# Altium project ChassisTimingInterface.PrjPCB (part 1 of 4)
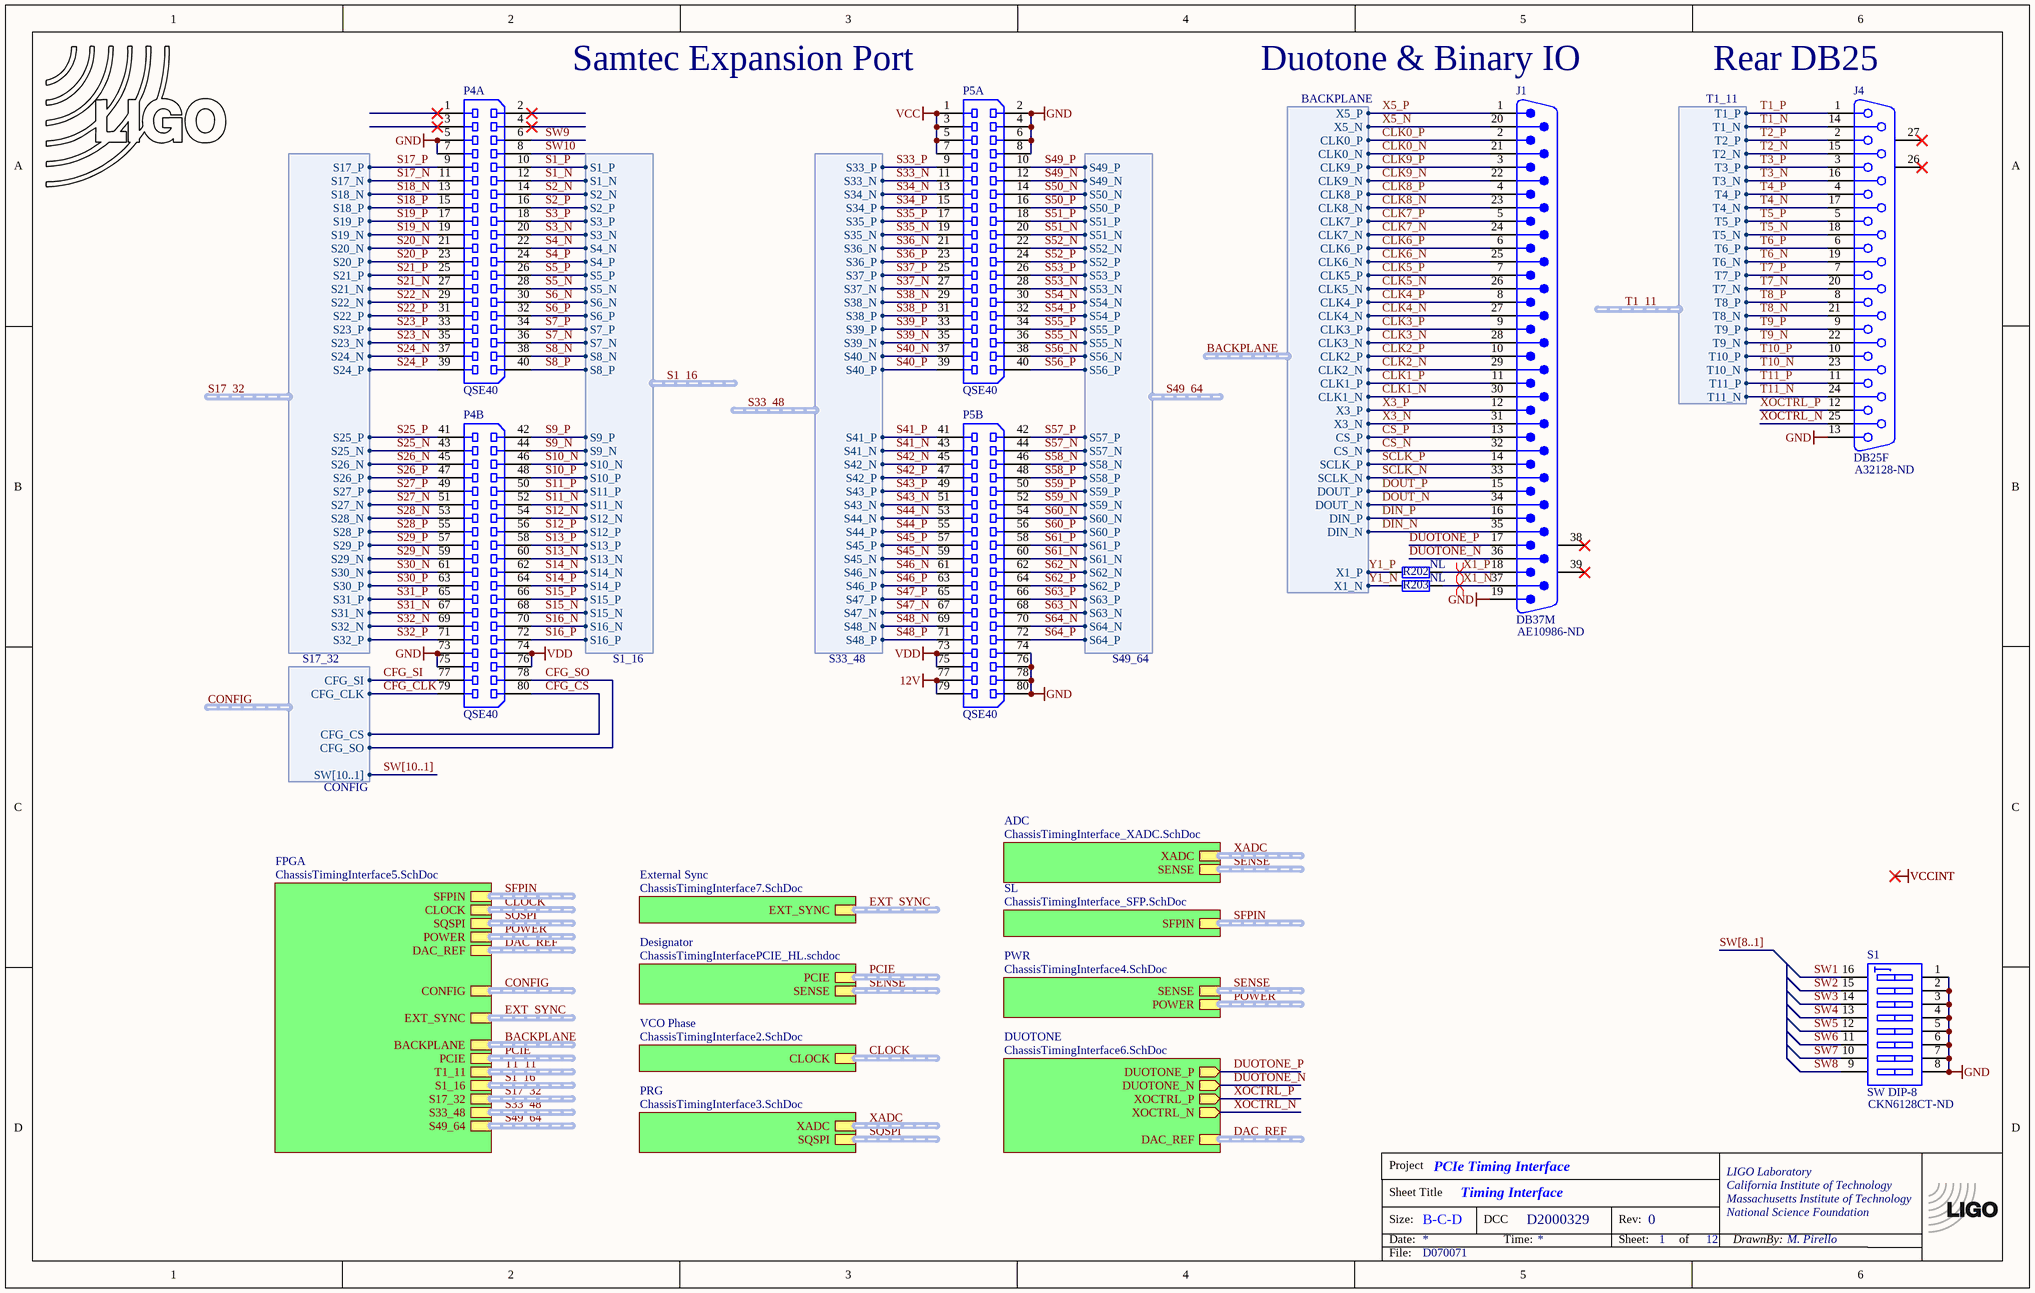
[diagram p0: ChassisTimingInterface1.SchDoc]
DCC: D2000329; Eng: M. Pirello; PROJECT: PCIe Timing Interface; REV: 0; SHEETSIZE: B-C-D
12 sheets, 566 parts. Net scope: hierarchical (ports join the sheet entries above them; power ports are global).
Board file: ChassisTimingInterface.PCBDOC
Sheets:
  ChassisTimingInterface1.SchDoc
    VCO Phase = ChassisTimingInterface2.SchDoc
    PWR = ChassisTimingInterface4.SchDoc
    PRG = ChassisTimingInterface3.SchDoc
    FPGA = ChassisTimingInterface5.SchDoc
      FPGA = FPGA_ARTIX7.SchDoc
    Designator = ChassisTimingInterfacePCIE_HL.SchDoc
      ChassisTimingInterfacePCIE = ChassisTimingInterfacePCIE.SchDoc
    DUOTONE = ChassisTimingInterface6.SchDoc
    SL = ChassisTimingInterface_SFP.SchDoc
    External Sync = ChassisTimingInterface7.SchDoc
    ADC = ChassisTimingInterface_XADC.SchDoc

## Sheet ChassisTimingInterface1.SchDoc: Timing Interface
size B; Engineer: Daniel Sigg; DocumentNumber: 1; Revision: C; SheetNumber: 1; SheetTotal: 12; PageSetup: Record=PageOptions¦CenterHorizontal=True¦CenterVertical=True¦PrintScale=0.72¦XCorrection=1.00¦YCorrection=1.00¦PrintKind=0¦BorderSize=5000000¦LeftOffset=0¦BottomOffset=0¦Orientation=2¦PaperLength=1000¦PaperWidth=1000¦Scale=100¦PaperSource=7¦PrintQuality=-4¦MediaType=1¦DitherType=10¦PaperKind=Tabloid¦PrintScaleMode=1

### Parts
(Parts that share a designator on the sheet are numbered #1, #2 ... from top to bottom, then left to right.)
*#1  TitleBlock  (value not drawn)  (graphical)
J1  DB37M  Supplier Part Number 1: AE10986-ND  [DB37M-RA]
J4  DB25F  Supplier Part Number 1: A32128-ND  [DB25F-RA]
LOGO1  LIGO logo  [LIGO-LOGO-SM]  (value not drawn)  (no BOM)
P4  QSE40  [QSE040]  (parts A,B of 2)
P5  QSE40  [QSE040]  (parts A,B of 2)
R202  NL  [CR1005-0402]
R203  NL  [CR1005-0402]
S1  SW DIP-8  Supplier Part Number 1: CKN6128CT-ND  [DIP_SW_8WAY_SMD_SIDE]

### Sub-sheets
ADC = ChassisTimingInterface_XADC.SchDoc: XADC (harness XADC), SENSE (harness SENSE)
Designator = ChassisTimingInterfacePCIE_HL.schdoc: PCIE (harness PCIE), SENSE (harness SENSE)
DUOTONE = ChassisTimingInterface6.SchDoc: DUOTONE_N (out), DUOTONE_P (out), XOCTRL_P (out), XOCTRL_N (out), DAC_REF (harness DAC_REF)
External Sync = ChassisTimingInterface7.SchDoc: EXT_SYNC (harness EXT_SYNC)
FPGA = ChassisTimingInterface5.SchDoc: S1_16 (harness S1_16), S17_32 (harness S17_32), S33_48 (harness S33_48), S49_64 (harness S49_64), T1_11 (harness T1_11), CLOCK (harness CLOCK), PCIE (harness PCIE), POWER (harness POWER), SQSPI (harness SQSPI), DAC_REF (harness DAC_REF), CONFIG (harness CONFIG), BACKPLANE (harness BACKPLANE), SFPIN (harness SFPIN), EXT_SYNC (harness EXT_SYNC)
PRG = ChassisTimingInterface3.SchDoc: SQSPI (harness SQSPI), XADC (harness XADC)
PWR = ChassisTimingInterface4.SchDoc: POWER (harness POWER), SENSE (harness SENSE)
SL = ChassisTimingInterface_SFP.SchDoc: SFPIN (harness SFPIN)
VCO Phase = ChassisTimingInterface2.SchDoc: CLOCK (harness CLOCK)

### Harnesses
S1_16: S1_N, S1_P, S2_N, S2_P, S3_N, S3_P, S4_N, S4_P, S5_N, S5_P, S6_N, S6_P, S7_N, S7_P, S8_N, S8_P, S9_N, S9_P, S10_N, S10_P, S11_N, S11_P, S12_N, S12_P, S13_N, S13_P, S14_N, S14_P, S15_N, S15_P, S16_N, S16_P
S17_32: S17_N, S17_P, S18_N, S18_P, S19_N, S19_P, S20_N, S20_P, S21_N, S21_P, S22_N, S22_P, S23_N, S23_P, S24_N, S24_P, S25_N, S25_P, S26_N, S26_P, S27_N, S27_P, S28_N, S28_P, S29_N, S29_P, S30_N, S30_P, S31_N, S31_P, S32_N, S32_P
S33_48: S33_P, S33_N, S34_P, S34_N, S35_P, S35_N, S36_N, S36_P, S37_P, S37_N, S38_N, S38_P, S39_P, S39_N, S40_N, S40_P, S41_P, S41_N, S42_N, S42_P, S43_P, S43_N, S44_N, S44_P, S45_P, S45_N, S46_N, S46_P, S47_P, S47_N, S48_N, S48_P
S49_64: S49_P, S49_N, S50_N, S50_P, S51_P, S51_N, S52_N, S52_P, S53_P, S53_N, S54_N, S54_P, S55_P, S55_N, S56_N, S56_P, S57_P, S57_N, S58_N, S58_P, S59_P, S59_N, S60_N, S60_P, S61_P, S61_N, S62_N, S62_P, S63_P, S63_N, S64_N, S64_P
T1_11: T1_P, T1_N, T2_P, T2_N, T3_P, T3_N, T4_P, T4_N, T5_P, T5_N, T6_P, T6_N, T7_P, T7_N, T8_P, T8_N, T9_P, T9_N, T10_P, T10_N, T11_P, T11_N
CONFIG: CFG_CLK, CFG_CS, CFG_SI, CFG_SO, SW[10..1]
BACKPLANE: DIN_N, DIN_P, DOUT_N, DOUT_P, SCLK_N, SCLK_P, CS_N, CS_P, X3_N, X3_P, CLK1_N, CLK1_P, CLK2_N, CLK2_P, CLK3_N, CLK3_P, CLK4_N, CLK4_P, CLK5_N, CLK5_P, CLK6_N, CLK6_P, CLK7_N, CLK7_P, CLK8_N, CLK8_P, CLK9_N, CLK9_P, CLK0_N, CLK0_P, X5_N, X5_P, X1_P, X1_N

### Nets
12V: P5.77 P5.79
GND: J1.19 J4.13 P4.5 P4.7 P4.73 P4.75 P4.81 P4.82 P4.83 P4.84 P4.85 P4.86 P4.87 P4.88 P5.2 P5.4 P5.6 P5.8 P5.74 P5.76 P5.78 P5.80 P5.81 P5.82 P5.83 P5.84 P5.85 P5.86 P5.87 P5.88 S1.1(A1) S1.2(A2) S1.3(A3) S1.4(A4) S1.5(A5) S1.6(A6) S1.7(A7) S1.8(A8)
VCC: P5.1 P5.3 P5.5 P5.7
VDD: P4.74 P4.76 P5.73 P5.75
CFG_CLK: P4.79 ; sheet FPGA/CONFIG.CFG_CLK
CFG_CS: P4.80 ; sheet FPGA/CONFIG.CFG_CS
CFG_SI: P4.77 ; sheet FPGA/CONFIG.CFG_SI
CFG_SO: P4.78 ; sheet FPGA/CONFIG.CFG_SO
CLK0_N: J1.21 ; sheet FPGA/BACKPLANE.CLK0_N  [project net BACKPLANE.CLK0_N]
CLK0_P: J1.2 ; sheet FPGA/BACKPLANE.CLK0_P  [project net BACKPLANE.CLK0_P]
CLK1_N: J1.30 ; sheet FPGA/BACKPLANE.CLK1_N  [project net BACKPLANE.CLK1_N]
CLK1_P: J1.11 ; sheet FPGA/BACKPLANE.CLK1_P  [project net BACKPLANE.CLK1_P]
CLK2_N: J1.29 ; sheet FPGA/BACKPLANE.CLK2_N  [project net BACKPLANE.CLK2_N]
CLK2_P: J1.10 ; sheet FPGA/BACKPLANE.CLK2_P  [project net BACKPLANE.CLK2_P]
CLK3_N: J1.28 ; sheet FPGA/BACKPLANE.CLK3_N  [project net BACKPLANE.CLK3_N]
CLK3_P: J1.9 ; sheet FPGA/BACKPLANE.CLK3_P  [project net BACKPLANE.CLK3_P]
CLK4_N: J1.27 ; sheet FPGA/BACKPLANE.CLK4_N  [project net BACKPLANE.CLK4_N]
CLK4_P: J1.8 ; sheet FPGA/BACKPLANE.CLK4_P  [project net BACKPLANE.CLK4_P]
CLK5_N: J1.26 ; sheet FPGA/BACKPLANE.CLK5_N  [project net BACKPLANE.CLK5_N]
CLK5_P: J1.7 ; sheet FPGA/BACKPLANE.CLK5_P  [project net BACKPLANE.CLK5_P]
CLK6_N: J1.25 ; sheet FPGA/BACKPLANE.CLK6_N  [project net BACKPLANE.CLK6_N]
CLK6_P: J1.6 ; sheet FPGA/BACKPLANE.CLK6_P  [project net BACKPLANE.CLK6_P]
CLK7_N: J1.24 ; sheet FPGA/BACKPLANE.CLK7_N  [project net BACKPLANE.CLK7_N]
CLK7_P: J1.5 ; sheet FPGA/BACKPLANE.CLK7_P  [project net BACKPLANE.CLK7_P]
CLK8_N: J1.23 ; sheet FPGA/BACKPLANE.CLK8_N  [project net BACKPLANE.CLK8_N]
CLK8_P: J1.4 ; sheet FPGA/BACKPLANE.CLK8_P  [project net BACKPLANE.CLK8_P]
CLK9_N: J1.22 ; sheet FPGA/BACKPLANE.CLK9_N  [project net BACKPLANE.CLK9_N]
CLK9_P: J1.3 ; sheet FPGA/BACKPLANE.CLK9_P  [project net BACKPLANE.CLK9_P]
CS_N: J1.32 ; sheet FPGA/BACKPLANE.CS_N  [project net BACKPLANE.CS_N]
CS_P: J1.13 ; sheet FPGA/BACKPLANE.CS_P  [project net BACKPLANE.CS_P]
DIN_N: J1.35 ; sheet FPGA/BACKPLANE.DIN_N  [project net BACKPLANE.DIN_N]
DIN_P: J1.16 ; sheet FPGA/BACKPLANE.DIN_P  [project net BACKPLANE.DIN_P]
DOUT_N: J1.34 ; sheet FPGA/BACKPLANE.DOUT_N  [project net BACKPLANE.DOUT_N]
DOUT_P: J1.15 ; sheet FPGA/BACKPLANE.DOUT_P  [project net BACKPLANE.DOUT_P]
DUOTONE_N: J1.36 ; sheet DUOTONE/DUOTONE_N
DUOTONE_P: J1.17 ; sheet DUOTONE/DUOTONE_P
S1_N: P4.12 ; sheet FPGA/S1_16.S1_N  [project net S1_16.S1_N]
S1_P: P4.10 ; sheet FPGA/S1_16.S1_P  [project net S1_16.S1_P]
S2_N: P4.14 ; sheet FPGA/S1_16.S2_N  [project net S1_16.S2_N]
S2_P: P4.16 ; sheet FPGA/S1_16.S2_P  [project net S1_16.S2_P]
S3_N: P4.20 ; sheet FPGA/S1_16.S3_N  [project net S1_16.S3_N]
S3_P: P4.18 ; sheet FPGA/S1_16.S3_P  [project net S1_16.S3_P]
S4_N: P4.22 ; sheet FPGA/S1_16.S4_N  [project net S1_16.S4_N]
S4_P: P4.24 ; sheet FPGA/S1_16.S4_P  [project net S1_16.S4_P]
S5_N: P4.28 ; sheet FPGA/S1_16.S5_N  [project net S1_16.S5_N]
S5_P: P4.26 ; sheet FPGA/S1_16.S5_P  [project net S1_16.S5_P]
S6_N: P4.30 ; sheet FPGA/S1_16.S6_N  [project net S1_16.S6_N]
S6_P: P4.32 ; sheet FPGA/S1_16.S6_P  [project net S1_16.S6_P]
S7_N: P4.36 ; sheet FPGA/S1_16.S7_N  [project net S1_16.S7_N]
S7_P: P4.34 ; sheet FPGA/S1_16.S7_P  [project net S1_16.S7_P]
S8_N: P4.38 ; sheet FPGA/S1_16.S8_N  [project net S1_16.S8_N]
S8_P: P4.40 ; sheet FPGA/S1_16.S8_P  [project net S1_16.S8_P]
S9_N: P4.44 ; sheet FPGA/S1_16.S9_N  [project net S1_16.S9_N]
S9_P: P4.42 ; sheet FPGA/S1_16.S9_P  [project net S1_16.S9_P]
S10_N: P4.46 ; sheet FPGA/S1_16.S10_N
S10_P: P4.48 ; sheet FPGA/S1_16.S10_P
S11_N: P4.52 ; sheet FPGA/S1_16.S11_N
S11_P: P4.50 ; sheet FPGA/S1_16.S11_P
S12_N: P4.54 ; sheet FPGA/S1_16.S12_N
S12_P: P4.56 ; sheet FPGA/S1_16.S12_P
S13_N: P4.60 ; sheet FPGA/S1_16.S13_N
S13_P: P4.58 ; sheet FPGA/S1_16.S13_P
S14_N: P4.62 ; sheet FPGA/S1_16.S14_N
S14_P: P4.64 ; sheet FPGA/S1_16.S14_P
S15_N: P4.68 ; sheet FPGA/S1_16.S15_N
S15_P: P4.66 ; sheet FPGA/S1_16.S15_P
S16_N: P4.70 ; sheet FPGA/S1_16.S16_N
S16_P: P4.72 ; sheet FPGA/S1_16.S16_P
S17_N: P4.11 ; sheet FPGA/S17_32.S17_N  [project net S17_32.S17_N]
S17_P: P4.9 ; sheet FPGA/S17_32.S17_P  [project net S17_32.S17_P]
S18_N: P4.13 ; sheet FPGA/S17_32.S18_N  [project net S17_32.S18_N]
S18_P: P4.15 ; sheet FPGA/S17_32.S18_P  [project net S17_32.S18_P]
S19_N: P4.19 ; sheet FPGA/S17_32.S19_N  [project net S17_32.S19_N]
S19_P: P4.17 ; sheet FPGA/S17_32.S19_P  [project net S17_32.S19_P]
S20_N: P4.21 ; sheet FPGA/S17_32.S20_N  [project net S17_32.S20_N]
S20_P: P4.23 ; sheet FPGA/S17_32.S20_P  [project net S17_32.S20_P]
S21_N: P4.27 ; sheet FPGA/S17_32.S21_N  [project net S17_32.S21_N]
S21_P: P4.25 ; sheet FPGA/S17_32.S21_P  [project net S17_32.S21_P]
S22_N: P4.29 ; sheet FPGA/S17_32.S22_N  [project net S17_32.S22_N]
S22_P: P4.31 ; sheet FPGA/S17_32.S22_P  [project net S17_32.S22_P]
S23_N: P4.35 ; sheet FPGA/S17_32.S23_N  [project net S17_32.S23_N]
S23_P: P4.33 ; sheet FPGA/S17_32.S23_P  [project net S17_32.S23_P]
S24_N: P4.37 ; sheet FPGA/S17_32.S24_N  [project net S17_32.S24_N]
S24_P: P4.39 ; sheet FPGA/S17_32.S24_P  [project net S17_32.S24_P]
S25_N: P4.43 ; sheet FPGA/S17_32.S25_N  [project net S17_32.S25_N]
S25_P: P4.41 ; sheet FPGA/S17_32.S25_P  [project net S17_32.S25_P]
S26_N: P4.45 ; sheet FPGA/S17_32.S26_N  [project net S17_32.S26_N]
S26_P: P4.47 ; sheet FPGA/S17_32.S26_P  [project net S17_32.S26_P]
S27_N: P4.51 ; sheet FPGA/S17_32.S27_N  [project net S17_32.S27_N]
S27_P: P4.49 ; sheet FPGA/S17_32.S27_P  [project net S17_32.S27_P]
S28_N: P4.53 ; sheet FPGA/S17_32.S28_N  [project net S17_32.S28_N]
S28_P: P4.55 ; sheet FPGA/S17_32.S28_P  [project net S17_32.S28_P]
S29_N: P4.59 ; sheet FPGA/S17_32.S29_N  [project net S17_32.S29_N]
S29_P: P4.57 ; sheet FPGA/S17_32.S29_P  [project net S17_32.S29_P]
S30_N: P4.61 ; sheet FPGA/S17_32.S30_N  [project net S17_32.S30_N]
S30_P: P4.63 ; sheet FPGA/S17_32.S30_P  [project net S17_32.S30_P]
S31_N: P4.67 ; sheet FPGA/S17_32.S31_N  [project net S17_32.S31_N]
S31_P: P4.65 ; sheet FPGA/S17_32.S31_P  [project net S17_32.S31_P]
S32_N: P4.69 ; sheet FPGA/S17_32.S32_N  [project net S17_32.S32_N]
S32_P: P4.71 ; sheet FPGA/S17_32.S32_P  [project net S17_32.S32_P]
S33_N: P5.11 ; sheet FPGA/S33_48.S33_N  [project net S33_48.S33_N]
S33_P: P5.9 ; sheet FPGA/S33_48.S33_P  [project net S33_48.S33_P]
S34_N: P5.13 ; sheet FPGA/S33_48.S34_N  [project net S33_48.S34_N]
S34_P: P5.15 ; sheet FPGA/S33_48.S34_P  [project net S33_48.S34_P]
S35_N: P5.19 ; sheet FPGA/S33_48.S35_N  [project net S33_48.S35_N]
S35_P: P5.17 ; sheet FPGA/S33_48.S35_P  [project net S33_48.S35_P]
S36_N: P5.21 ; sheet FPGA/S33_48.S36_N  [project net S33_48.S36_N]
S36_P: P5.23 ; sheet FPGA/S33_48.S36_P  [project net S33_48.S36_P]
S37_N: P5.27 ; sheet FPGA/S33_48.S37_N  [project net S33_48.S37_N]
S37_P: P5.25 ; sheet FPGA/S33_48.S37_P  [project net S33_48.S37_P]
S38_N: P5.29 ; sheet FPGA/S33_48.S38_N  [project net S33_48.S38_N]
S38_P: P5.31 ; sheet FPGA/S33_48.S38_P  [project net S33_48.S38_P]
S39_N: P5.35 ; sheet FPGA/S33_48.S39_N  [project net S33_48.S39_N]
S39_P: P5.33 ; sheet FPGA/S33_48.S39_P  [project net S33_48.S39_P]
S40_N: P5.37 ; sheet FPGA/S33_48.S40_N  [project net S33_48.S40_N]
S40_P: P5.39 ; sheet FPGA/S33_48.S40_P  [project net S33_48.S40_P]
S41_N: P5.43 ; sheet FPGA/S33_48.S41_N  [project net S33_48.S41_N]
S41_P: P5.41 ; sheet FPGA/S33_48.S41_P  [project net S33_48.S41_P]
S42_N: P5.45 ; sheet FPGA/S33_48.S42_N  [project net S33_48.S42_N]
S42_P: P5.47 ; sheet FPGA/S33_48.S42_P  [project net S33_48.S42_P]
S43_N: P5.51 ; sheet FPGA/S33_48.S43_N  [project net S33_48.S43_N]
S43_P: P5.49 ; sheet FPGA/S33_48.S43_P  [project net S33_48.S43_P]
S44_N: P5.53 ; sheet FPGA/S33_48.S44_N  [project net S33_48.S44_N]
S44_P: P5.55 ; sheet FPGA/S33_48.S44_P  [project net S33_48.S44_P]
S45_N: P5.59 ; sheet FPGA/S33_48.S45_N  [project net S33_48.S45_N]
S45_P: P5.57 ; sheet FPGA/S33_48.S45_P  [project net S33_48.S45_P]
S46_N: P5.61 ; sheet FPGA/S33_48.S46_N  [project net S33_48.S46_N]
S46_P: P5.63 ; sheet FPGA/S33_48.S46_P  [project net S33_48.S46_P]
S47_N: P5.67 ; sheet FPGA/S33_48.S47_N  [project net S33_48.S47_N]
S47_P: P5.65 ; sheet FPGA/S33_48.S47_P  [project net S33_48.S47_P]
S48_N: P5.69 ; sheet FPGA/S33_48.S48_N  [project net S33_48.S48_N]
S48_P: P5.71 ; sheet FPGA/S33_48.S48_P  [project net S33_48.S48_P]
S49_N: P5.12 ; sheet FPGA/S49_64.S49_N  [project net S49_64.S49_N]
S49_P: P5.10 ; sheet FPGA/S49_64.S49_P  [project net S49_64.S49_P]
S50_N: P5.14 ; sheet FPGA/S49_64.S50_N  [project net S49_64.S50_N]
S50_P: P5.16 ; sheet FPGA/S49_64.S50_P  [project net S49_64.S50_P]
S51_N: P5.20 ; sheet FPGA/S49_64.S51_N  [project net S49_64.S51_N]
S51_P: P5.18 ; sheet FPGA/S49_64.S51_P  [project net S49_64.S51_P]
S52_N: P5.22 ; sheet FPGA/S49_64.S52_N  [project net S49_64.S52_N]
S52_P: P5.24 ; sheet FPGA/S49_64.S52_P  [project net S49_64.S52_P]
S53_N: P5.28 ; sheet FPGA/S49_64.S53_N  [project net S49_64.S53_N]
S53_P: P5.26 ; sheet FPGA/S49_64.S53_P  [project net S49_64.S53_P]
S54_N: P5.30 ; sheet FPGA/S49_64.S54_N  [project net S49_64.S54_N]
S54_P: P5.32 ; sheet FPGA/S49_64.S54_P  [project net S49_64.S54_P]
S55_N: P5.36 ; sheet FPGA/S49_64.S55_N  [project net S49_64.S55_N]
S55_P: P5.34 ; sheet FPGA/S49_64.S55_P  [project net S49_64.S55_P]
S56_N: P5.38 ; sheet FPGA/S49_64.S56_N  [project net S49_64.S56_N]
S56_P: P5.40 ; sheet FPGA/S49_64.S56_P  [project net S49_64.S56_P]
S57_N: P5.44 ; sheet FPGA/S49_64.S57_N  [project net S49_64.S57_N]
S57_P: P5.42 ; sheet FPGA/S49_64.S57_P  [project net S49_64.S57_P]
S58_N: P5.46 ; sheet FPGA/S49_64.S58_N  [project net S49_64.S58_N]
S58_P: P5.48 ; sheet FPGA/S49_64.S58_P  [project net S49_64.S58_P]
S59_N: P5.52 ; sheet FPGA/S49_64.S59_N  [project net S49_64.S59_N]
S59_P: P5.50 ; sheet FPGA/S49_64.S59_P  [project net S49_64.S59_P]
S60_N: P5.54 ; sheet FPGA/S49_64.S60_N  [project net S49_64.S60_N]
S60_P: P5.56 ; sheet FPGA/S49_64.S60_P  [project net S49_64.S60_P]
S61_N: P5.60 ; sheet FPGA/S49_64.S61_N  [project net S49_64.S61_N]
S61_P: P5.58 ; sheet FPGA/S49_64.S61_P  [project net S49_64.S61_P]
S62_N: P5.62 ; sheet FPGA/S49_64.S62_N  [project net S49_64.S62_N]
S62_P: P5.64 ; sheet FPGA/S49_64.S62_P  [project net S49_64.S62_P]
S63_N: P5.68 ; sheet FPGA/S49_64.S63_N  [project net S49_64.S63_N]
S63_P: P5.66 ; sheet FPGA/S49_64.S63_P  [project net S49_64.S63_P]
S64_N: P5.70 ; sheet FPGA/S49_64.S64_N  [project net S49_64.S64_N]
S64_P: P5.72 ; sheet FPGA/S49_64.S64_P  [project net S49_64.S64_P]
SCLK_N: J1.33 ; sheet FPGA/BACKPLANE.SCLK_N  [project net BACKPLANE.SCLK_N]
SCLK_P: J1.14 ; sheet FPGA/BACKPLANE.SCLK_P  [project net BACKPLANE.SCLK_P]
SW1: S1.16(B1)
SW2: S1.15(B2)
SW3: S1.14(B3)
SW4: S1.13(B4)
SW5: S1.12(B5)
SW6: S1.11(B6)
SW7: S1.10(B7)
SW8: S1.9(B8)
SW9: P4.6
SW10: P4.8
T1_N: J4.14 ; sheet FPGA/T1_11.T1_N  [project net T1_11.T1_N]
T1_P: J4.1 ; sheet FPGA/T1_11.T1_P  [project net T1_11.T1_P]
T2_N: J4.15 ; sheet FPGA/T1_11.T2_N  [project net T1_11.T2_N]
T2_P: J4.2 ; sheet FPGA/T1_11.T2_P  [project net T1_11.T2_P]
T3_N: J4.16 ; sheet FPGA/T1_11.T3_N  [project net T1_11.T3_N]
T3_P: J4.3 ; sheet FPGA/T1_11.T3_P  [project net T1_11.T3_P]
T4_N: J4.17 ; sheet FPGA/T1_11.T4_N  [project net T1_11.T4_N]
T4_P: J4.4 ; sheet FPGA/T1_11.T4_P  [project net T1_11.T4_P]
T5_N: J4.18 ; sheet FPGA/T1_11.T5_N  [project net T1_11.T5_N]
T5_P: J4.5 ; sheet FPGA/T1_11.T5_P  [project net T1_11.T5_P]
T6_N: J4.19 ; sheet FPGA/T1_11.T6_N  [project net T1_11.T6_N]
T6_P: J4.6 ; sheet FPGA/T1_11.T6_P  [project net T1_11.T6_P]
T7_N: J4.20 ; sheet FPGA/T1_11.T7_N  [project net T1_11.T7_N]
T7_P: J4.7 ; sheet FPGA/T1_11.T7_P  [project net T1_11.T7_P]
T8_N: J4.21 ; sheet FPGA/T1_11.T8_N  [project net T1_11.T8_N]
T8_P: J4.8 ; sheet FPGA/T1_11.T8_P  [project net T1_11.T8_P]
T9_N: J4.22 ; sheet FPGA/T1_11.T9_N  [project net T1_11.T9_N]
T9_P: J4.9 ; sheet FPGA/T1_11.T9_P  [project net T1_11.T9_P]
T10_N: J4.23 ; sheet FPGA/T1_11.T10_N
T10_P: J4.10 ; sheet FPGA/T1_11.T10_P
T11_N: J4.24 ; sheet FPGA/T1_11.T11_N
T11_P: J4.11 ; sheet FPGA/T1_11.T11_P
X1_N: J1.37 R203.2
X1_P: J1.18 R202.2
X3_N: J1.31 ; sheet FPGA/BACKPLANE.X3_N  [project net BACKPLANE.X3_N]
X3_P: J1.12 ; sheet FPGA/BACKPLANE.X3_P  [project net BACKPLANE.X3_P]
X5_N: J1.20 ; sheet FPGA/BACKPLANE.X5_N  [project net BACKPLANE.X5_N]
X5_P: J1.1 ; sheet FPGA/BACKPLANE.X5_P  [project net BACKPLANE.X5_P]
XOCTRL_N: J4.25 ; sheet DUOTONE/XOCTRL_N
XOCTRL_P: J4.12 ; sheet DUOTONE/XOCTRL_P
Y1_N: R203.1 ; sheet FPGA/BACKPLANE.X1_N  [project net BACKPLANE.X1_N]
Y1_P: R202.1 ; sheet FPGA/BACKPLANE.X1_P  [project net BACKPLANE.X1_P]

Not connected (* = marked no-connect by the designer): J1 38* 39*; J4 26(MH1)* 27(MH2)*; P4 1* 2* 3* 4*

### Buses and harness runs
bus SW[8..1]
bus SW[10..1]
harness BACKPLANE = sheet FPGA/BACKPLANE
harness CLOCK = sheet FPGA/CLOCK
harness CLOCK = sheet VCO Phase/CLOCK
harness CONFIG = sheet FPGA/CONFIG
harness DAC_REF = sheet DUOTONE/DAC_REF
harness DAC_REF = sheet FPGA/DAC_REF
harness EXT_SYNC = sheet External Sync/EXT_SYNC
harness EXT_SYNC = sheet FPGA/EXT_SYNC
harness PCIE = sheet Designator/PCIE
harness PCIE = sheet FPGA/PCIE
harness POWER = sheet FPGA/POWER
harness POWER = sheet PWR/POWER
harness S1_16 = sheet FPGA/S1_16
harness S17_32 = sheet FPGA/S17_32
harness S33_48 = sheet FPGA/S33_48
harness S49_64 = sheet FPGA/S49_64
harness SENSE = sheet ADC/SENSE
harness SENSE = sheet Designator/SENSE
harness SENSE = sheet PWR/SENSE
harness SFPIN = sheet FPGA/SFPIN
harness SFPIN = sheet SL/SFPIN
harness SQSPI = sheet FPGA/SQSPI
harness SQSPI = sheet PRG/SQSPI
harness T1_11 = sheet FPGA/T1_11
harness XADC = sheet ADC/XADC
harness XADC = sheet PRG/XADC

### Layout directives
differential pair: X1_N, X1_P

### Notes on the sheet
- (near P5) Samtec Expansion Port
- (near J1) Duotone & Binary IO
- (near J4) Rear DB25

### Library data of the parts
J1 = DB37M: Plug Assembly, 37 Position, Right Angle, .318 Series; Part Number: A32104-ND
J4 = DB25F: Receptacle Assembly, 25 Position, Right Angle, .318 Series
LOGO1 = LIGO_logo
P4 P5 = SAMTEC_QSE40: Samtec hi-speed socket, 0.8mm, 80 pins; Part Number: SAM8124-ND
R202 R203 = ChipRes1: Resistor, surface mount; Tolerance: 0.1%
S1 = SW DIP-8: DIP Switch, 8 Position, SPST

## Sheet ChassisTimingInterface2.SchDoc: VCO & Phase Detector
size B; DocumentNumber: 2; Revision: C; SheetNumber: 2; SheetTotal: 12
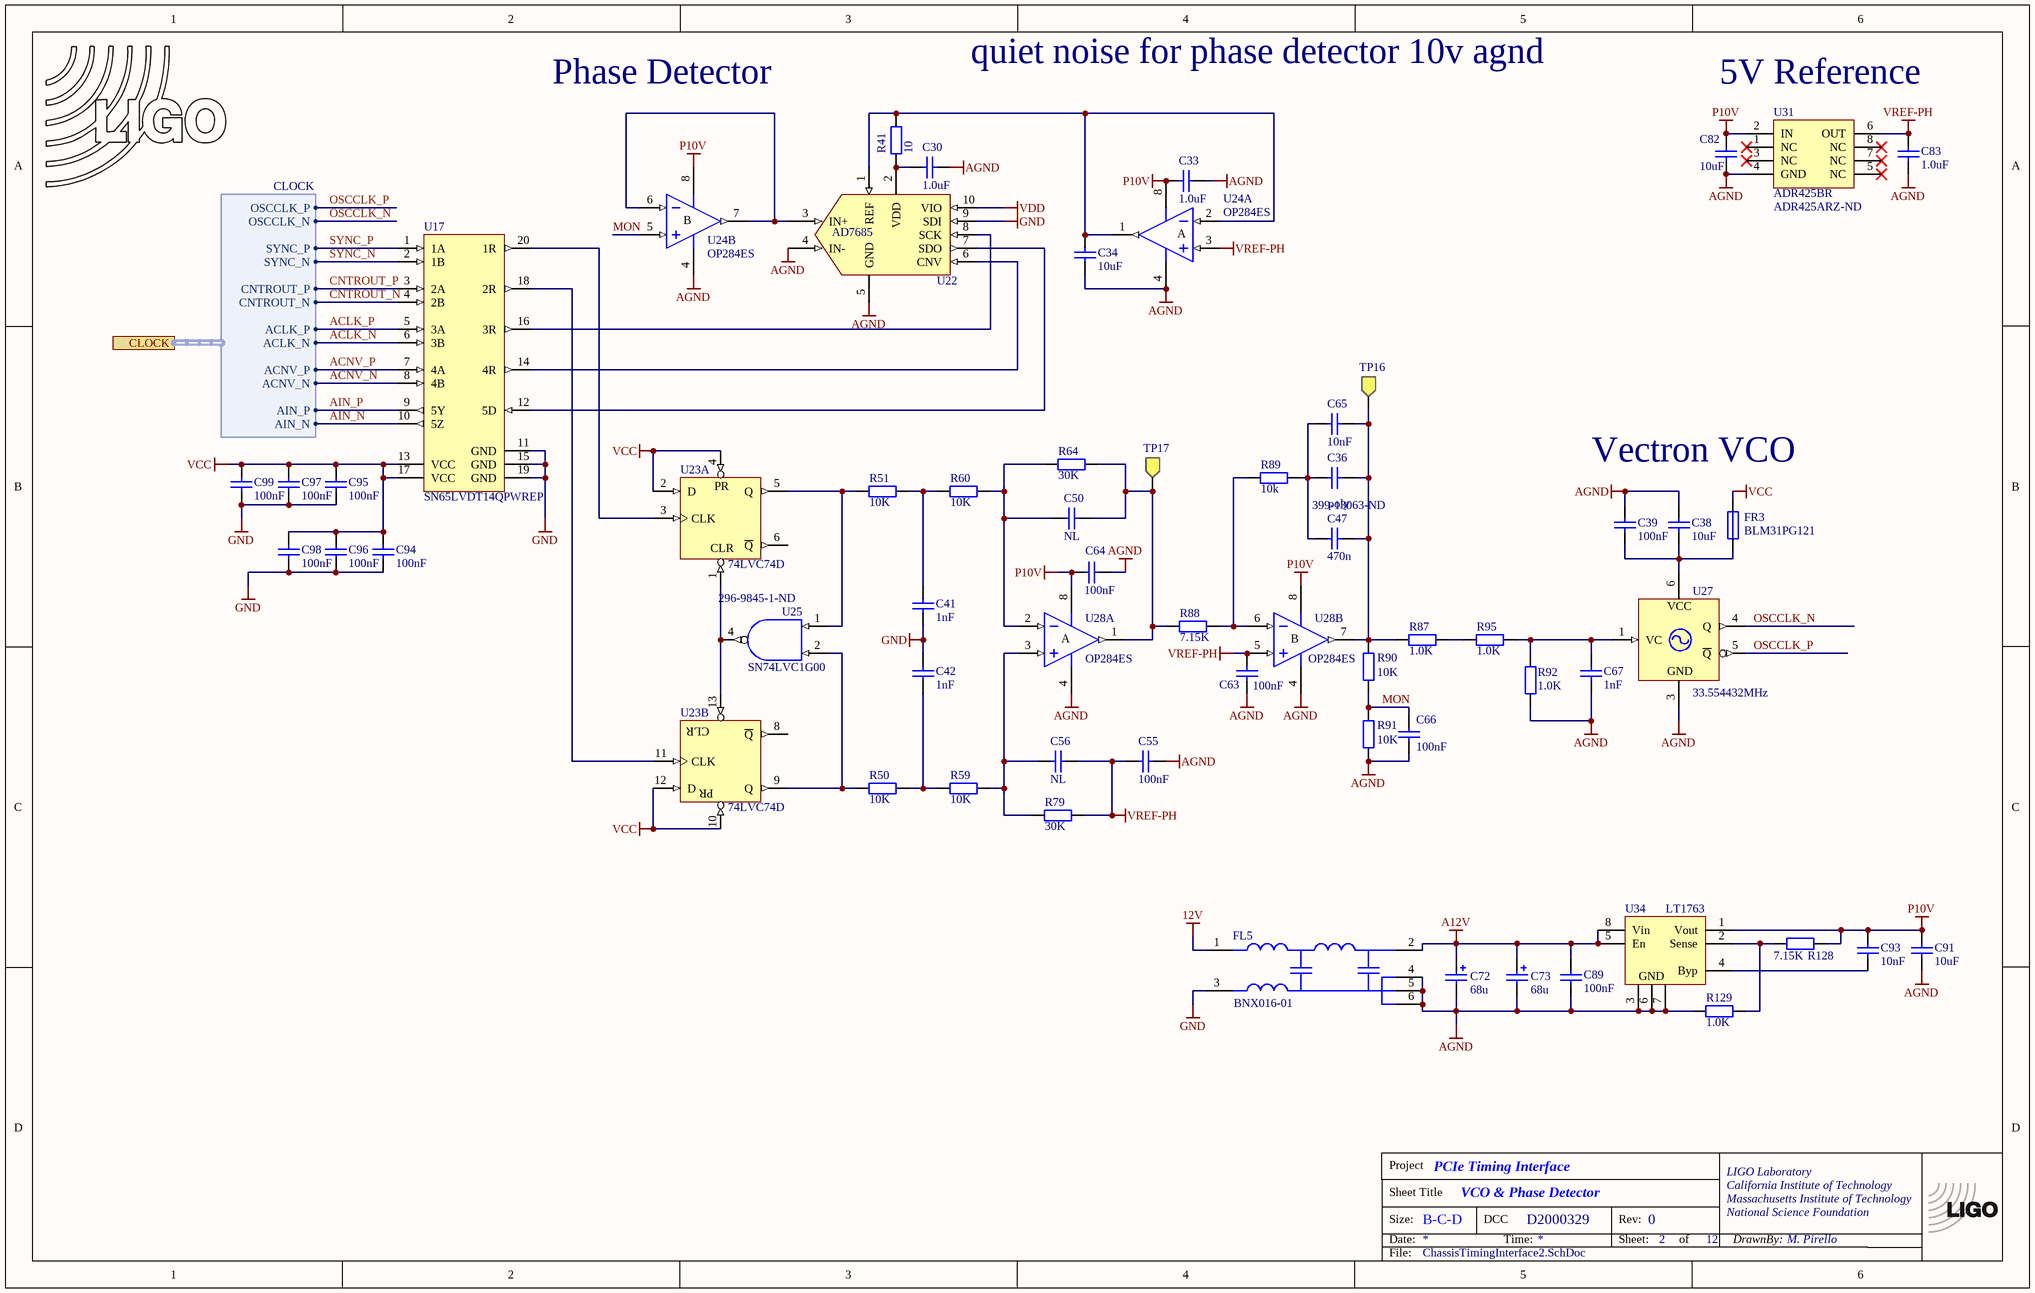
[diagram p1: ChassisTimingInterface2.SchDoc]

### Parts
(Parts that share a designator on the sheet are numbered #1, #2 ... from top to bottom, then left to right.)
*?#1  TitleBlock  (value not drawn)  (graphical)
C30  1.0uF  [CC1608-0603]
C33  1.0uF  [CC1608-0603]
C34  10uF  [CC2013-0805]
C36  (no value)  [CA053035]
C38  10uF  [CC2013-0805]
C39  100nF  [CC1005-0402]
C41  1nF  [CC1005-0402]
C42  1nF  [CC1005-0402]
C47  Supplier Part Number 1: 399-13063-ND  [ECQPZ120060-5.0]  (hidden comment: 470n)
C50  NL  [CC2013-0805]
C55  100nF  [CC1005-0402]
C56  NL  [CC2013-0805]
C63  100nF  [CC1005-0402]
C64  100nF  [CC1005-0402]
C65  10nF  [CC1005-0402]
C66  100nF  [CC1005-0402]
C67  1nF  [CC1005-0402]
C72  68u  [TC7343-2917]
C73  68u  [TC7343-2917]
C82  10uF  [CC2013-0805]
C83  1.0uF  [CC1608-0603]
C89  100nF  [CC1005-0402]
C91  10uF  [CC2013-0805]
C93  10nF  [CC1005-0402]
C94  100nF  [CC1005-0402]
C95  100nF  [CC1005-0402]
C96  100nF  [CC1005-0402]
C97  100nF  [CC1005-0402]
C98  100nF  [CC1005-0402]
C99  100nF  [CC1005-0402]
FL5  BNX016-01  [MURA-BNX016-01_V]
FR3  BLM31PG121  [CC3216-1206]
LOGO2  LIGO logo  [LIGO_LOGO]  (value not drawn)  (graphical)
R41  value 10  [CR1005-0402]  (hidden comment: 10.0)
R50  10K  [CR1005-0402]
R51  10K  [CR1005-0402]
R59  10K  [CR1005-0402]
R60  10K  [CR1005-0402]
R64  30K  [CR2012-0805]
R79  30K  [CR2012-0805]
R87  1.0K  [CR1608-0603]
R88  7.15K  [CR1005-0402]
R89  10k  [CR1005-0402]
R90  10K  [CR1005-0402]
R91  10K  [CR1005-0402]
R92  1.0K  [CR1608-0603]
R95  1.0K  [CR1608-0603]
R128  7.15K  [CR1005-0402]
R129  1.0K  [CR1608-0603]
TP16  Testpoint  [TP1-YLW]  (value not drawn)
TP17  Testpoint  [TP1-YLW]  (value not drawn)
U17  SN65LVDT14QPWREP  [PW0020A_N]
U22  AD7685  [TSSO3x5-G10]
U23  74LVC74D  [TSSOP14]  (parts A,B of 2)
U24  OP284ES  [SO-8_N]  (parts A,B of 2)
U25  SN74LVC1G00  Supplier Part Number 1: 296-9845-1-ND  [SO-G5/E2.4]
U27  33.554432MHz  [VECTRON_C5310]
U28  OP284ES  [SO-8_N]  (parts A,B of 2)
U31  ADR425BR  Supplier Part Number 1: ADR425ARZ-ND  [SO-G8]
U34  LT1763  [SO-G8]

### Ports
CLOCK (harness CLOCK)

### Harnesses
CLOCK: OSCCLK_N, OSCCLK_P, CNTROUT_N, CNTROUT_P, SYNC_N, SYNC_P, ACLK_P, ACLK_N, ACNV_P, ACNV_N, AIN_P, AIN_N

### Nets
12V: FL5.1(B)
A12V: C72.1 C73.1 C89.2 FL5.2(CB) U34.5(En) U34.8(Vin)
AGND: C30.1 C33.1 C34.2 C38.1 C39.1 C55.1 C63.1 C64.1 C66.1 C67.2 C72.2 C73.2 C82.2 C83.1 C89.1 C91.2 FL5.4(CG) FL5.5(CG) FL5.6(CG) R91.2 R92.2 R129.2 U22.4(IN-) U22.5(GND) U24.4(V-) U27.3(GND) U28.4(V-) U31.4(GND) U34.3(GND) U34.6(GND) U34.7(GND)
GND: C41.2 C42.1 C94.1 C95.1 C96.1 C97.1 C98.1 C99.1 FL5.3(PSG) U17.11(GND) U17.15(GND) U17.19(GND) U22.9(SDI) U23.7(GND) U25.3(GND)
P10V: C33.2 C64.2 C82.1 C91.1 C93.1 R128.2 U24.8(V+) U28.8(V+) U31.2(IN) U34.1(Vout)
VCC: C94.2 C95.2 C96.2 C97.2 C98.2 C99.2 FR3.2 U17.13(VCC) U17.17(VCC) U23.2(D) U23.4(PR) U23.10(PR) U23.12(D) U23.14(VCC) U25.5(VCC)
VDD: U22.10(VIO)
VREF-PH: C55.2 C56.1 C63.2 C83.2 R79.2 U24.3(IN+) U28.5(IN+) U31.6(OUT)
ACLK_N: U17.6(3B) ; port CLOCK.ACLK_N  [project net CLOCK.ACLK_N]
ACLK_P: U17.5(3A) ; port CLOCK.ACLK_P  [project net CLOCK.ACLK_P]
ACNV_N: U17.8(4B) ; port CLOCK.ACNV_N  [project net CLOCK.ACNV_N]
ACNV_P: U17.7(4A) ; port CLOCK.ACNV_P  [project net CLOCK.ACNV_P]
AIN_N: U17.10(5Z) ; port CLOCK.AIN_N  [project net CLOCK.AIN_N]
AIN_P: U17.9(5Y) ; port CLOCK.AIN_P  [project net CLOCK.AIN_P]
CNTROUT_N: U17.4(2B) ; port CLOCK.CNTROUT_N  [project net CLOCK.CNTROUT_N]
CNTROUT_P: U17.3(2A) ; port CLOCK.CNTROUT_P  [project net CLOCK.CNTROUT_P]
MON: C66.2 R90.2 R91.1 U24.5(IN+)
OSCCLK_N: U27.4(Q) ; port CLOCK.OSCCLK_N  [project net CLOCK.OSCCLK_N]
OSCCLK_P: U27.5(~{Q}) ; port CLOCK.OSCCLK_P  [project net CLOCK.OSCCLK_P]
SYNC_N: U17.2(1B) ; port CLOCK.SYNC_N  [project net CLOCK.SYNC_N]
SYNC_P: U17.1(1A) ; port CLOCK.SYNC_P  [project net CLOCK.SYNC_P]
NetC30_2: C30.2 R41.1 U22.2(VDD)
NetC34_1: C34.1 R41.2 U22.1(REF) U24.1(OUT) U24.2(IN-)
NetC36_1: C36.1 C47.1 C65.2 R89.2
NetC36_2: C36.2 C47.2 C65.1 R87.2 R90.1 TP16.1 U28.7(OUT)
NetC38_2: C38.2 C39.2 FR3.1 U27.6(VDD)
NetC41_1: C41.1 R51.2 R60.1
NetC42_2: C42.2 R50.2 R59.1
NetC50_1: C50.1 R64.2 R88.1 TP17.1 U28.1(OUT)
NetC50_2: C50.2 R60.2 R64.1 U28.2(IN-)
NetC56_2: C56.2 R59.2 R79.1 U28.3(IN+)
NetC67_1: C67.1 R92.1 R95.1 U27.1(VC)
NetC93_2: C93.2 U34.4(Byp)
NetR50_1: R50.1 U23.9(Q) U25.2
NetR51_1: R51.1 U23.5(Q) U25.1
NetR87_1: R87.1 R95.2
NetR88_2: R88.2 R89.1 U28.6(IN-)
NetR128_1: R128.1 R129.1 U34.2(Sense)
NetU17_12: U17.12(5D) U22.7(SDO)
NetU17_14: U17.14(4R) U22.6(CNV)
NetU17_16: U17.16(3R) U22.8(SCK)
NetU17_18: U17.18(2R) U23.11(CLK)
NetU17_20: U17.20(1R) U23.3(CLK)
NetU22_3: U22.3(IN+) U24.6(IN-) U24.7(OUT)
NetU23_1: U23.1(CLR) U23.13(CLR) U25.4

Not connected (* = marked no-connect by the designer): U23 6(~{Q}) 8(~{Q}); U27 2(NC); U31 1(NC)* 3(NC)* 5(NC)* 7(NC)* 8(NC)*

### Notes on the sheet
- Phase Detector
- quiet noise for phase detector 10v agnd
- 5V Reference
- poly
- Vectron VCO

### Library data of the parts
C30 C33 C83 = ChipCap: C0603 1.0uF; Part Number: 1276-1184-1-ND; Tolerance: 10%
C34 C38 C82 C91 = ChipCap: C0805 10uF; Part Number: 1276-6454-1-ND; Tolerance: 10%
C36 = CapFilmAxial: Film Capacitor, axial lead; Part Number: MCO2B474G; Tolerance: 2%
C39 C55 C63 C64 C66 C89 C94-C99 = ChipCap: C0402 0.1uF; Part Number: 1276-6720-1-ND; Tolerance: 10%
C41 C42 C67 = ChipCap: C0402 1.0nF; Part Number: 1292-1246-1-ND; Tolerance: 10%
C47 = CapPolypropylene ECQPZ: Polypropylene Film Capacitor, radial lead; Tolerance: 2%
C50 C56 = ChipCap: Capacitor, surface mount
C65 C93 = ChipCap: C0402 0.01uF; Part Number: 311-1349-1-ND; Tolerance: 10%
C72 C73 = ChipTantalum: Tantalum capacitor, surface mount; Part Number: 399-3908-1-ND; Tolerance: 20%
FL5 = CMP-2000-05960-1: Block Type EMIFIL(R) Reference Specification, 15 A, 25 V, -40 to 125 degC, 6-Pin THD, RoHS, Bulk; Part Number: 490-5055-ND
FR3 = BLM31PG121SN1: ferrite bead, 120Ohm at 100MHz, 1206; Part Number: 490-1056-1-ND
LOGO2 = LIGO_logo
R41 = ChipRes1: R0402 10; Part Number: A127127CT-ND; Tolerance: 0.1%
R50 R51 R59 R60 R89-R91 = ChipRes1: R0402 10k; Part Number: RR05P10.0KDCT-ND; Tolerance: 0.1%
R64 R79 = ChipRes1: R0805 30k; Part Number: RR12P30.0KDCT-ND; Tolerance: 0.1%
R87 R92 R95 R129 = ChipRes1: R0603 1.0k; Part Number: RR08P1.0KDCT-ND; Tolerance: 0.1%
R88 R128 = ChipRes1: R0402 7.15k; Part Number: YAG1478CT-ND; Tolerance: 0.1%
TP16 TP17 = TP_SIGNAL: Testpoint, yellow; Part Number: 36-5004-ND
U17 = CMP-0327-00205-3: 125 Mbps Enhanced Product Memorystick? Interconnect Extender Chipset with LVDS and LVTTL, 1 Tx and 4 Rx, -55 to +125 degC, 20-pin TSSOP (PW), Green (RoHS & no Sb/Br); Part Number: 296-19499-1-ND
U22 = AD7685: 16 bit ADC, 250kSPS, pseudo differential, serial; Part Number: AD7685ARMZRL7CT-ND
U23 = 74F74PC: Dual D-Type Positive Edge-Triggered Flip-Flop; Part Number: 296-1240-5-ND
U24 U28 = OP284ES: Precision Rail-to-Rail Input and Output Operational Amplifier; Part Number: OP284ESZ-REEL7TR-ND
U27 = VECTRON_C5310: Voltage controlled crystal oscillator; Part Number: C5310-D105-SV033-RFL-B1-67.108864MHz
U31 = ADR292ER: Low-Noise Micropower Precision Voltage Reference
U34 = LT1763: Positive voltage regulator; Part Number: LT1763CS8#PBF-ND

## Sheet ChassisTimingInterface4.SchDoc: Power Supply
size B; DocumentNumber: 5; Revision: C; SheetNumber: 4; SheetTotal: 12
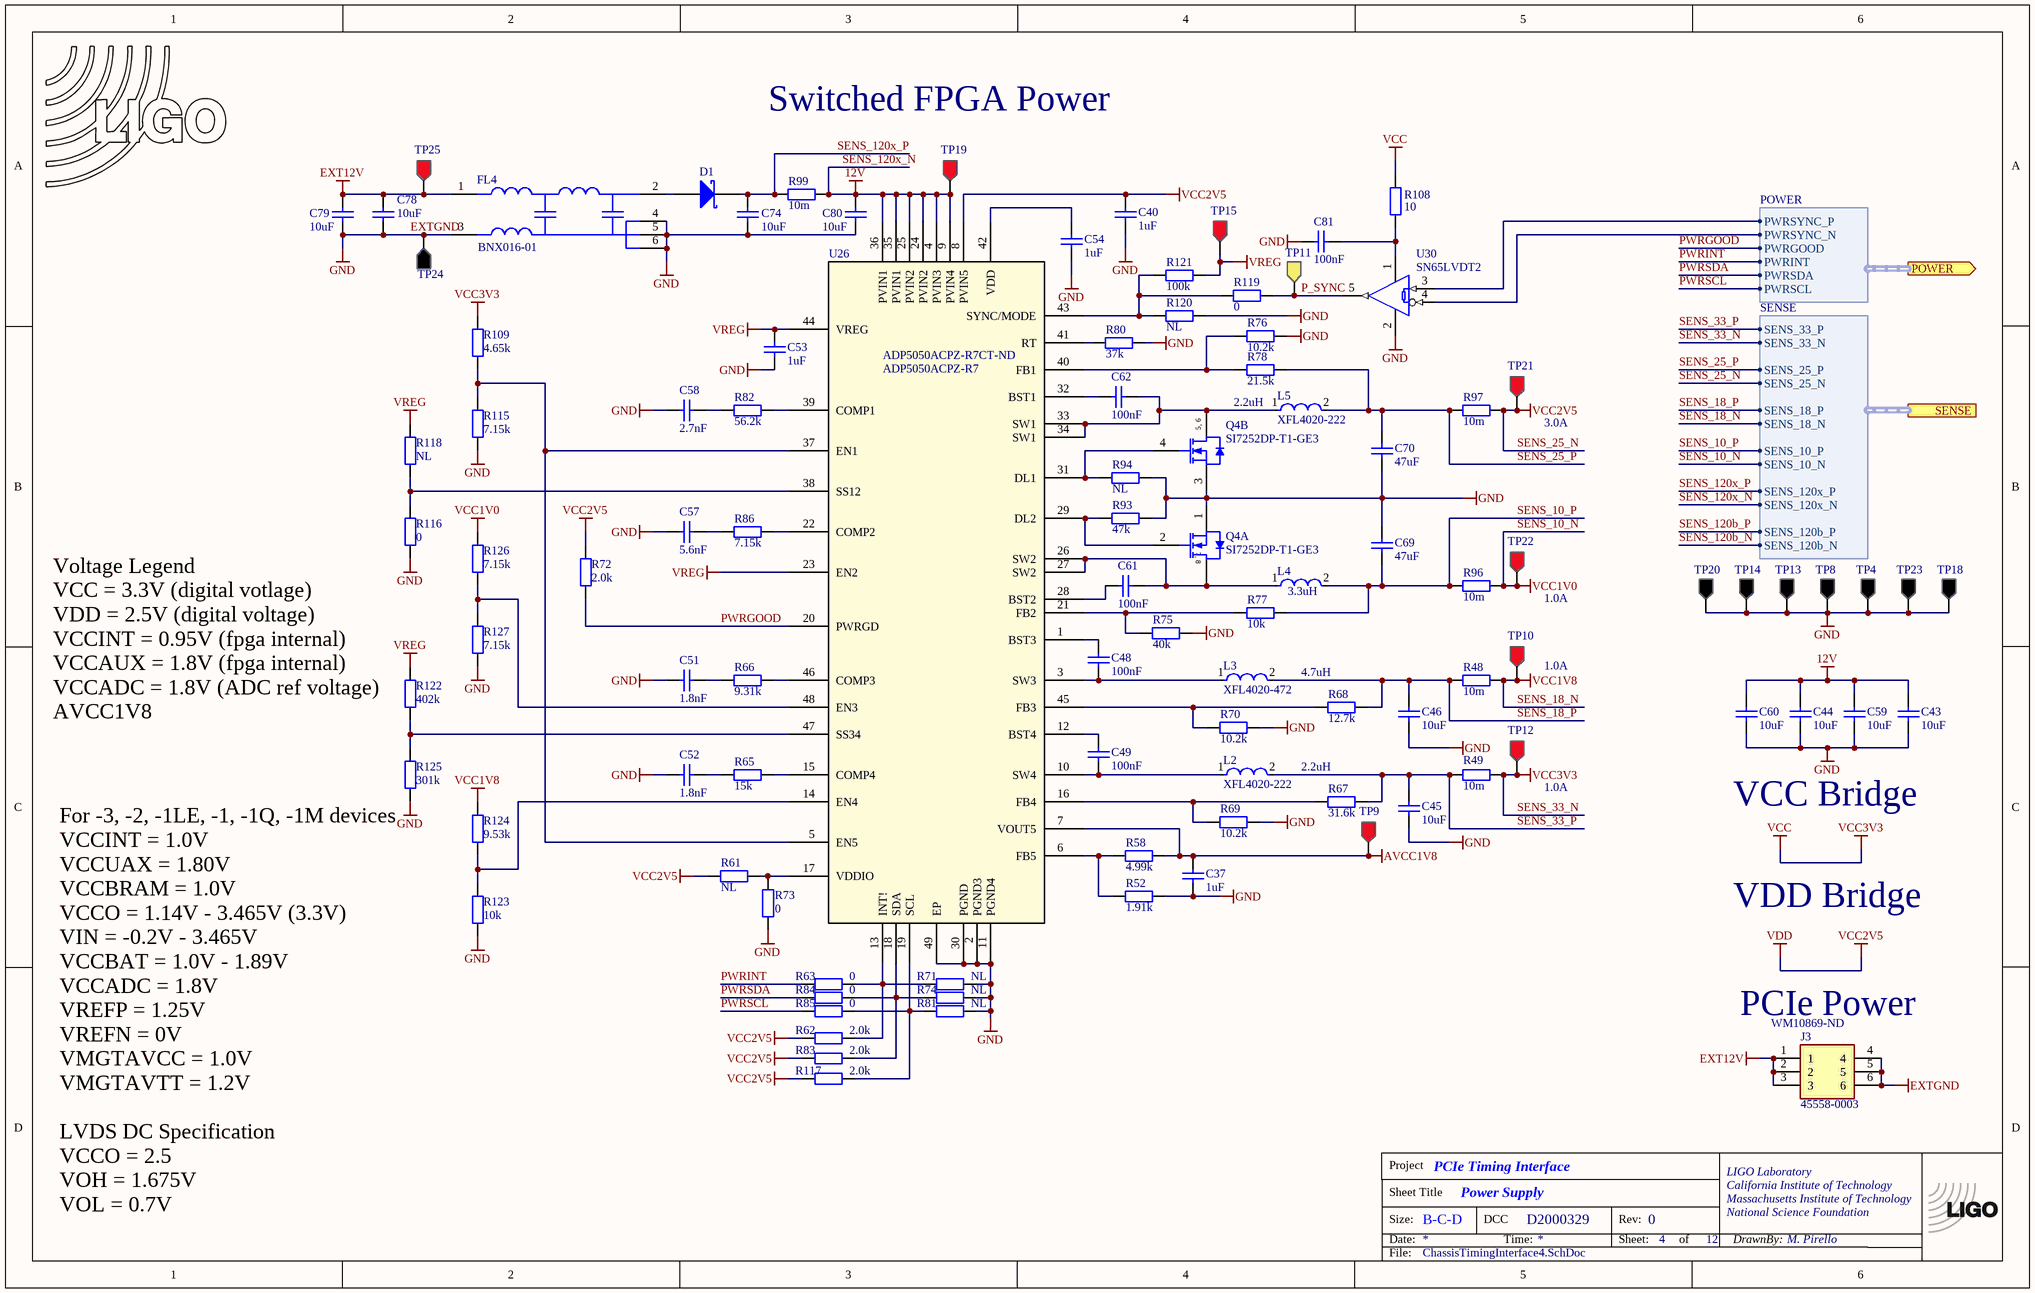
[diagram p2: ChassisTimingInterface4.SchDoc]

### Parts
(Parts that share a designator on the sheet are numbered #1, #2 ... from top to bottom, then left to right.)
*#2  TitleBlock  (value not drawn)  (graphical)
C37  value 1uF  [CC1005-0402]  (hidden comment: 1.0u)
C40  value 1uF  [CC1005-0402]  (hidden comment: 1.0u)
C43  10uF  [CC2013-0805]
C44  10uF  [CC2013-0805]
C45  10uF  [CC2013-0805]
C46  10uF  [CC2013-0805]
C48  100nF  [CC1005-0402]
C49  100nF  [CC1005-0402]
C51  1.8nF  [CC1005-0402]
C52  1.8nF  [CC1005-0402]
C53  value 1uF  [CC1005-0402]  (hidden comment: 1.0u)
C54  value 1uF  [CC1005-0402]  (hidden comment: 1.0u)
C57  5.6nF  [CC1005-0402]
C58  2.7nF  [CC1005-0402]
C59  10uF  [CC2013-0805]
C60  10uF  [CC2013-0805]
C61  100nF  [CC1005-0402]
C62  100nF  [CC1005-0402]
C69  47uF  [CC3216-1206]
C70  47uF  [CC3216-1206]
C74  10uF  [CC2013-0805]
C78  10uF  [CC2013-0805]
C79  10uF  [CC2013-0805]
C80  10uF  [CC2013-0805]
C81  100nF  [CC1005-0402]
D1  LSM115JE3/TR13  [MCSM-DO-214BA-2_L]  (value not drawn)
FL4  BNX016-01  [MURA-BNX016-01_V]
J3  45558-0003  Supplier Part Number 1: WM10869-ND  [455580003]
L2  XFL4020-222  [FP-XAL40-MFG]
L3  XFL4020-472  [FP-XAL40-MFG]
L4  XFL4020-332  [FP-XAL40-MFG]  (value not drawn)
L5  XFL4020-222  [FP-XAL40-MFG]
LOGO4#1  LIGO logo  [LIGO_LOGO]  (value not drawn)  (graphical)
Q4  SI7252DP-T1-GE3  [VISH-POWERPAKSO-8_A_V]  (parts A,B of 2)
R48  10m  [CC3216-1206]
R49  10m  [CC3216-1206]
R52  1.91k  [CR1005-0402]
R58  4.99k  [CR1608-0603]
R61  NL  [CR1005-0402]
R62  2.0k  [CR1005-0402]
R63  0  [CR1005-0402]
R65  15k  [CR1005-0402]
R66  9.31k  [CR1005-0402]
R67  31.6k  [CR1005-0402]
R68  12.7k  [CR1005-0402]
R69  value 10.2k  [CR1005-0402]  (hidden comment: 10k)
R70  value 10.2k  [CR1005-0402]  (hidden comment: 10k)
R71  NL  [CR1005-0402]
R72  2.0k  [CR1005-0402]
R73  0  [CR1005-0402]
R74  NL  [CR1005-0402]
R75  value 40k  [CR1005-0402]  (hidden comment: 40.2k)
R76  value 10.2k  [CR1005-0402]  (hidden comment: 10k)
R77  10k  [CR1005-0402]
R78  21.5k  [CR1005-0402]
R80  value 37k  [CR1005-0402]  (hidden comment: 37.4k)
R81  NL  [CR1005-0402]
R82  56.2k  [CR1005-0402]
R83  2.0k  [CR1005-0402]
R84  0  [CR1005-0402]
R85  0  [CR1005-0402]
R86  7.15k  [CR1005-0402]
R93  47k  [CR1005-0402]
R94  NL  [CR1005-0402]
R96  10m  [CC3216-1206]
R97  10m  [CC3216-1206]
R99  10m  [CC3216-1206]
R108  value 10  [CR1005-0402]  (hidden comment: 10.0)
R109  value 4.65k  [CR1005-0402]  (hidden comment: 4.7k)
R115  7.15k  [CR1005-0402]
R116  0  [CR1005-0402]
R117#1  2.0k  [CR1005-0402]
R118#1  NL  [CR1005-0402]
R119#1  0  [CR1005-0402]
R120  NL  [CR1005-0402]
R121  100k  [CR1005-0402]
R122  402k  [CR1005-0402]
R123  10k  [CR1005-0402]
R124  9.53k  [CR1005-0402]
R125  301k  [CR1005-0402]
R126  7.15k  [CR1005-0402]
R127  7.15k  [CR1005-0402]
TP4  Testpoint  [TP1-BLK]  (value not drawn)
TP8  Testpoint  [TP1-BLK]  (value not drawn)
TP9  Testpoint  [TP1-RED]  (value not drawn)
TP10  Testpoint  [TP1-RED]  (value not drawn)
TP11  Testpoint  [TP1-YLW]  (value not drawn)
TP12  Testpoint  [TP1-RED]  (value not drawn)
TP13  Testpoint  [TP1-BLK]  (value not drawn)
TP14  Testpoint  [TP1-BLK]  (value not drawn)
TP15  Testpoint  [TP1-RED]  (value not drawn)
TP18  Testpoint  [TP1-BLK]  (value not drawn)
TP19  Testpoint  [TP1-RED]  (value not drawn)
TP20  Testpoint  [TP1-BLK]  (value not drawn)
TP21  Testpoint  [TP1-RED]  (value not drawn)
TP22  Testpoint  [TP1-RED]  (value not drawn)
TP23  Testpoint  [TP1-BLK]  (value not drawn)
TP24  Testpoint  [TP1-BLK]  (value not drawn)
TP25  Testpoint  [TP1-RED]  (value not drawn)
U26  ADP5050ACPZ-R7  Supplier Part Number 1: ADP5050ACPZ-R7CT-ND  [CP-48-13_L]
U30  SN65LVDT2  [SO-G5/E2.4]

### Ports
POWER (out, harness POWER), SENSE (harness SENSE)

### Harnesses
POWER: PWRSYNC_N, PWRSYNC_P, PWRGOOD, PWRINT, PWRSDA, PWRSCL
SENSE: SENS_33_P, SENS_33_N, SENS_25_P, SENS_25_N, SENS_18_P, SENS_18_N, SENS_10_P, SENS_10_N, SENS_120x_P, SENS_120x_N, SENS_120b_P, SENS_120b_N

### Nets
12V: C43.1 C44.1 C59.1 C60.1 C80.1 R99.2 TP19.1 U26.4(PVIN3) U26.9(PVIN4) U26.24(PVIN2) U26.25(PVIN2) U26.35(PVIN1) U26.36(PVIN1) ; port SENSE.SENS_120x_N, port SENSE.SENS_120b_N  [also labelled SENS_120b_N, SENS_120x_N]
AVCC1V8: C37.2 R58.2 TP9.1 U26.7(VOUT5)
EXT12V: C78.1 C79.1 FL4.1(B) J3.1 J3.2 J3.3 TP25.1
GND: C37.1 C40.1 C43.2 C44.2 C45.1 C46.1 C51.1 C52.1 C53.2 C54.1 C57.1 C58.1 C59.2 C60.2 C69.2 C70.1 C74.2 C78.2 C79.2 C80.2 C81.2 FL4.3(PSG) FL4.4(CG) FL4.5(CG) FL4.6(CG) J3.4 J3.5 J3.6 Q4.1(S1) Q4.3(S2) R52.2 R69.2 R70.2 R71.2 R73.1 R74.2 R75.2 R76.2 R80.2 R81.2 R93.2 R94.2 R115.1 R116.1 R120.2 R123.1 R125.1 R127.1 TP4.1 TP8.1 TP13.1 TP14.1 TP18.1 TP20.1 TP23.1 TP24.1 U26.2(PGND3) U26.11(PGND4) U26.30(PGND) U26.49(EP) U30.2(GND)  [also labelled EXTGND]
SENS_10_N: R96.2 R126.2 TP22.1 ; port SENSE.SENS_10_N  [also labelled VCC1V0]  [project net VCCINT]
VCC: R49.2 R108.2 R109.2 TP12.1 ; port SENSE.SENS_33_N  [also labelled SENS_33_N, VCC3V3]
VCC1V8: R48.2 R124.2 TP10.1 ; port SENSE.SENS_18_N  [also labelled SENS_18_N]
VDD: C40.2 R61.2 R62.1 R72.2 R83.1 R97.2 R117#1.1 TP21.1 U26.8(PVIN5) ; port SENSE.SENS_25_N  [also labelled SENS_25_N, VCC2V5]
VREG: C53.1 R118#1.2 R121.2 R122.2 TP15.1 U26.23(EN2) U26.44(VREG)
P_SYNC: R119#1.2 TP11.1 U30.5(R)
POWER.PWRSYNC_N: U30.4(B) ; port POWER.PWRSYNC_N
POWER.PWRSYNC_P: U30.3(A) ; port POWER.PWRSYNC_P
PWRGOOD: R72.1 U26.20(PWRGD) ; port POWER.PWRGOOD  [project net POWER.PWRGOOD]
PWRINT: R63.1 ; port POWER.PWRINT  [project net POWER.PWRINT]
PWRSCL: R85.1 ; port POWER.PWRSCL  [project net POWER.PWRSCL]
PWRSDA: R84.1 ; port POWER.PWRSDA  [project net POWER.PWRSDA]
SENS_10_P: C69.1 L4.2 R77.2 R96.1 ; port SENSE.SENS_10_P  [project net SENSE.SENS_10_P]
SENS_18_P: C46.2 L3.2 R48.1 R68.2 ; port SENSE.SENS_18_P  [project net SENSE.SENS_18_P]
SENS_25_P: C70.2 L5.2 R78.2 R97.1 ; port SENSE.SENS_25_P  [project net SENSE.SENS_25_P]
SENS_33_P: C45.2 L2.2 R49.1 R67.2 ; port SENSE.SENS_33_P  [project net SENSE.SENS_33_P]
SENS_120x_P: C74.1 D1.2(K) R99.1 ; port SENSE.SENS_120x_P  [project net SENSE.SENS_120x_P]
NetC48_1: C48.1 L3.1 U26.3(SW3)
NetC48_2: C48.2 U26.1(BST3)
NetC49_1: C49.1 L2.1 U26.10(SW4)
NetC49_2: C49.2 U26.12(BST4)
NetC51_2: C51.2 R66.1
NetC52_2: C52.2 R65.1
NetC54_2: C54.2 U26.42(VDD)
NetC57_2: C57.2 R86.1
NetC58_2: C58.2 R82.1
NetC61_1: C61.1 U26.28(BST2)
NetC61_2: C61.2 L4.1 Q4.7(D1) Q4.8(D1) U26.26(SW2) U26.27(SW2)
NetC62_1: C62.1 U26.32(BST1)
NetC62_2: C62.2 L5.1 Q4.5(D2) Q4.6(D2) U26.33(SW1) U26.34(SW1)
NetC81_1: C81.1 R108.1 U30.1(VCC)
NetD1_1: D1.1(A) FL4.2(CB)
NetQ4_2: Q4.2(G1) R93.1 U26.29(DL2)
NetQ4_4: Q4.4(G2) R94.1 U26.31(DL1)
NetR52_1: R52.1 R58.1 U26.6(FB5)
NetR61_1: R61.1 R73.2 U26.17(VDDIO)
NetR62_2: R62.2 R63.2 R71.1 U26.13(INT!)
NetR65_2: R65.2 U26.15(COMP4)
NetR66_2: R66.2 U26.46(COMP3)
NetR67_1: R67.1 R69.1 U26.16(FB4)
NetR68_1: R68.1 R70.1 U26.45(FB3)
NetR74_1: R74.1 R83.2 R84.2 U26.18(SDA)
NetR75_1: R75.1 R77.1 U26.21(FB2)
NetR76_1: R76.1 R78.1 U26.40(FB1)
NetR80_1: R80.1 U26.41(RT)
NetR81_1: R81.1 R85.2 R117#1.2 U26.19(SCL)
NetR82_2: R82.2 U26.39(COMP1)
NetR86_2: R86.2 U26.22(COMP2)
NetR109_1: R109.1 R115.2 U26.5(EN5) U26.37(EN1)
NetR116_2: R116.2 R118#1.1 U26.38(SS12)
NetR119#1_1: R119#1.1 R120.1 R121.1 U26.43(SYNC/MODE)
NetR122_1: R122.1 R125.2 U26.47(SS34)
NetR123_2: R123.2 R124.1 U26.14(EN4)
NetR126_1: R126.1 R127.2 U26.48(EN3)

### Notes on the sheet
- Switched FPGA Power
- 2.2uH
- 3.0A
- (near L4) 3.3uH
- 1.0A
- 4.7uH
- (near TP10) 1.0A
- Voltage Legend
  VCC = 3.3V (digital votlage)
  VDD = 2.5V (digital voltage)
  VCCINT = 0.95V (fpga internal)
  VCCAUX = 1.8V (fpga internal)
  VCCADC = 1.8V (ADC ref voltage)
  AVCC1V8
- VCC Bridge
- VDD Bridge
- (near J3) PCIe Power
- (near R125) For -3, -2, -1LE, -1, -1Q, -1M devices
  VCCINT = 1.0V
  VCCUAX = 1.80V
  VCCBRAM = 1.0V
  VCCO = 1.14V - 3.465V (3.3V)
  VIN = -0.2V - 3.465V
  VCCBAT = 1.0V - 1.89V
  VCCADC = 1.8V
  VREFP = 1.25V
  VREFN = 0V
  VMGTAVCC = 1.0V
  VMGTAVTT = 1.2V
  LVDS DC Specification
  VCCO = 2.5
  VOH = 1.675V
  VOL = 0.7V

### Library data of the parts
C37 C40 C53 C54 = ChipCap: C0402 1.0uF; Part Number: 490-10017-1-ND; Tolerance: 10%
C43-C46 C59 C60 C74 C78-C80 = ChipCap: as C34 on sheet ChassisTimingInterface2
C48 C49 C61 C62 C81 = ChipCap: as C39 on sheet ChassisTimingInterface2
C51 C52 = ChipCap: C0402 1.8nF; Part Number: 399-17370-1-ND; Tolerance: 10%
C57 = ChipCap: C0402 5.6nF; Part Number: 1276-1578-1-ND; Tolerance: 10%
C58 = ChipCap: C0402 2.7nF; Part Number: 399-14439-1-ND; Tolerance: 10%
C69 C70 = ChipCap: C1206 47uF; Part Number: 490-16268-1-ND; Tolerance: 10%
D1 = CMP-2000-06604-1: Ultra Low Forward Voltage Schottky Rectifier, 15 V, -55 to 100 degC, 2-Pin Molded, RoHS, Tape and Reel; Part Number: LSM115JE3/TR13CT-ND
FL4 = CMP-2000-05960-1: as FL5 on sheet ChassisTimingInterface2
J3 = 45558-0003: Connector
L2 L5 = CMP-11268-000008-1: INDUCTOR, 2.2uH; Value: 10uH; Tolerance: 20%
L3 = CMP-11268-000008-1: INDUCTOR, 4.7uH; Value: 10uH; Tolerance: 20%
L4 = CMP-11268-000008-1: INDUCTOR, 3.3uH; Value: 10uH; Tolerance: 20%
LOGO4#1 = LIGO_logo
Q4 = CMP-2000-07602-1: Dual N-Channel (D-S) MOSFET, 100 V, 36.7 A, -55 to 150 degC, 8-Pin SMD, RoHS, Tape and Reel; Part Number: SI7252DP-T1-GE3CT-ND
R48 R49 R96 R97 R99 = ChipRes1: R1206 10m; Part Number: 273-PCS1206DR0100ETCT-ND; Tolerance: 0.1%
R52 = ChipRes1: R0402 1.91k; Part Number: YAG4201CT-ND; Tolerance: 0.1%
R58 = ChipRes1: R0603 4.99k; Part Number: RR08P4.99KDCT-ND; Tolerance: 0.1%
R61 R71 R74 R81 R94 R118#1 R120 = ChipRes1: Resistor, surface mount; Tolerance: 0.1%
R62 R72 R83 R117#1 = ChipRes1: R0402 2.0k; Part Number: RG10P2.00KDCT-ND; Tolerance: 0.1%
R63 R73 R84 R85 R116 R119#1 = ChipRes1: R0402 0; Part Number: 541-2877-1-ND; Tolerance: 0.1%
R65 = ChipRes1: R0402 15k; Part Number: RR05P15.0KDCT-ND; Tolerance: 0.1%
R66 = ChipRes1: R0402 9.31k; Part Number: 311-2336-1-ND; Tolerance: 0.1%
R67 = ChipRes1: R0402 31.6k; Part Number: 311-2272-1-ND; Tolerance: 0.1%
R68 = ChipRes1: R0402 12.7k; Part Number: RNCF0402DTE12K7CT-ND; Tolerance: 0.1%
R69 R70 R76 R77 R123 = ChipRes1: as R50 on sheet ChassisTimingInterface2
R75 = ChipRes1: R0402 40.2k; Part Number: P18270CT-ND; Tolerance: 0.1%
R78 = ChipRes1: R0402 21.5K; Part Number: RNCF0402DTE21K5CT-ND; Tolerance: 0.1%
R80 = ChipRes1: R0402 37.4k; Part Number: YAG4250CT-ND; Tolerance: 0.1%
R82 = ChipRes1: R0402 56.2k; Part Number: 311-2303-1-ND; Tolerance: 0.1%
R86 R115 R126 R127 = ChipRes1: as R88 on sheet ChassisTimingInterface2
R93 = ChipRes1: R0402 47k; Part Number: RG10P47KBCT-ND; Tolerance: 0.1%
R108 = ChipRes1: as R41 on sheet ChassisTimingInterface2
R109 = ChipRes1: R0402 4.7k; Part Number: RR05P4.7KDCT-ND; Tolerance: 0.1%
R121 = ChipRes1: R0402 100k; Part Number: RR05P100KDCT-ND; Tolerance: 0.1%
R122 = ChipRes1: R0402 402k; Part Number: RMCF0402FT402KCT-ND; Tolerance: 0.1%
R124 = ChipRes1: R0402 9.31k; Part Number: YAG4326CT-ND; Tolerance: 0.1%
R125 = ChipRes1: R0402 301k; Part Number: RMCF0402FT301KCT-ND; Tolerance: 0.1%
TP4 TP8 TP13 TP14 TP18 TP20 TP23 TP24 = TP_GND: Testpoint, black; Part Number: 36-5001-ND
TP9 TP10 TP12 TP15 TP19 TP21 TP22 TP25 = TP_POSITIVE: Testpoint, red; Part Number: 36-5000-ND
TP11 = TP_SIGNAL: as TP16 on sheet ChassisTimingInterface2
U26 = ADP5050ACPZ-R7: Artix 7 Power Supply
U30 = SN65LVDT2DBV: Single LVDS Receiver with 100 Ohm termination; Part Number: 296-6896-1-ND

## Sheet ChassisTimingInterface3.SchDoc: JTAG & SPI Flash
size B; DocumentNumber: 4; Revision: C; SheetNumber: 3; SheetTotal: 12
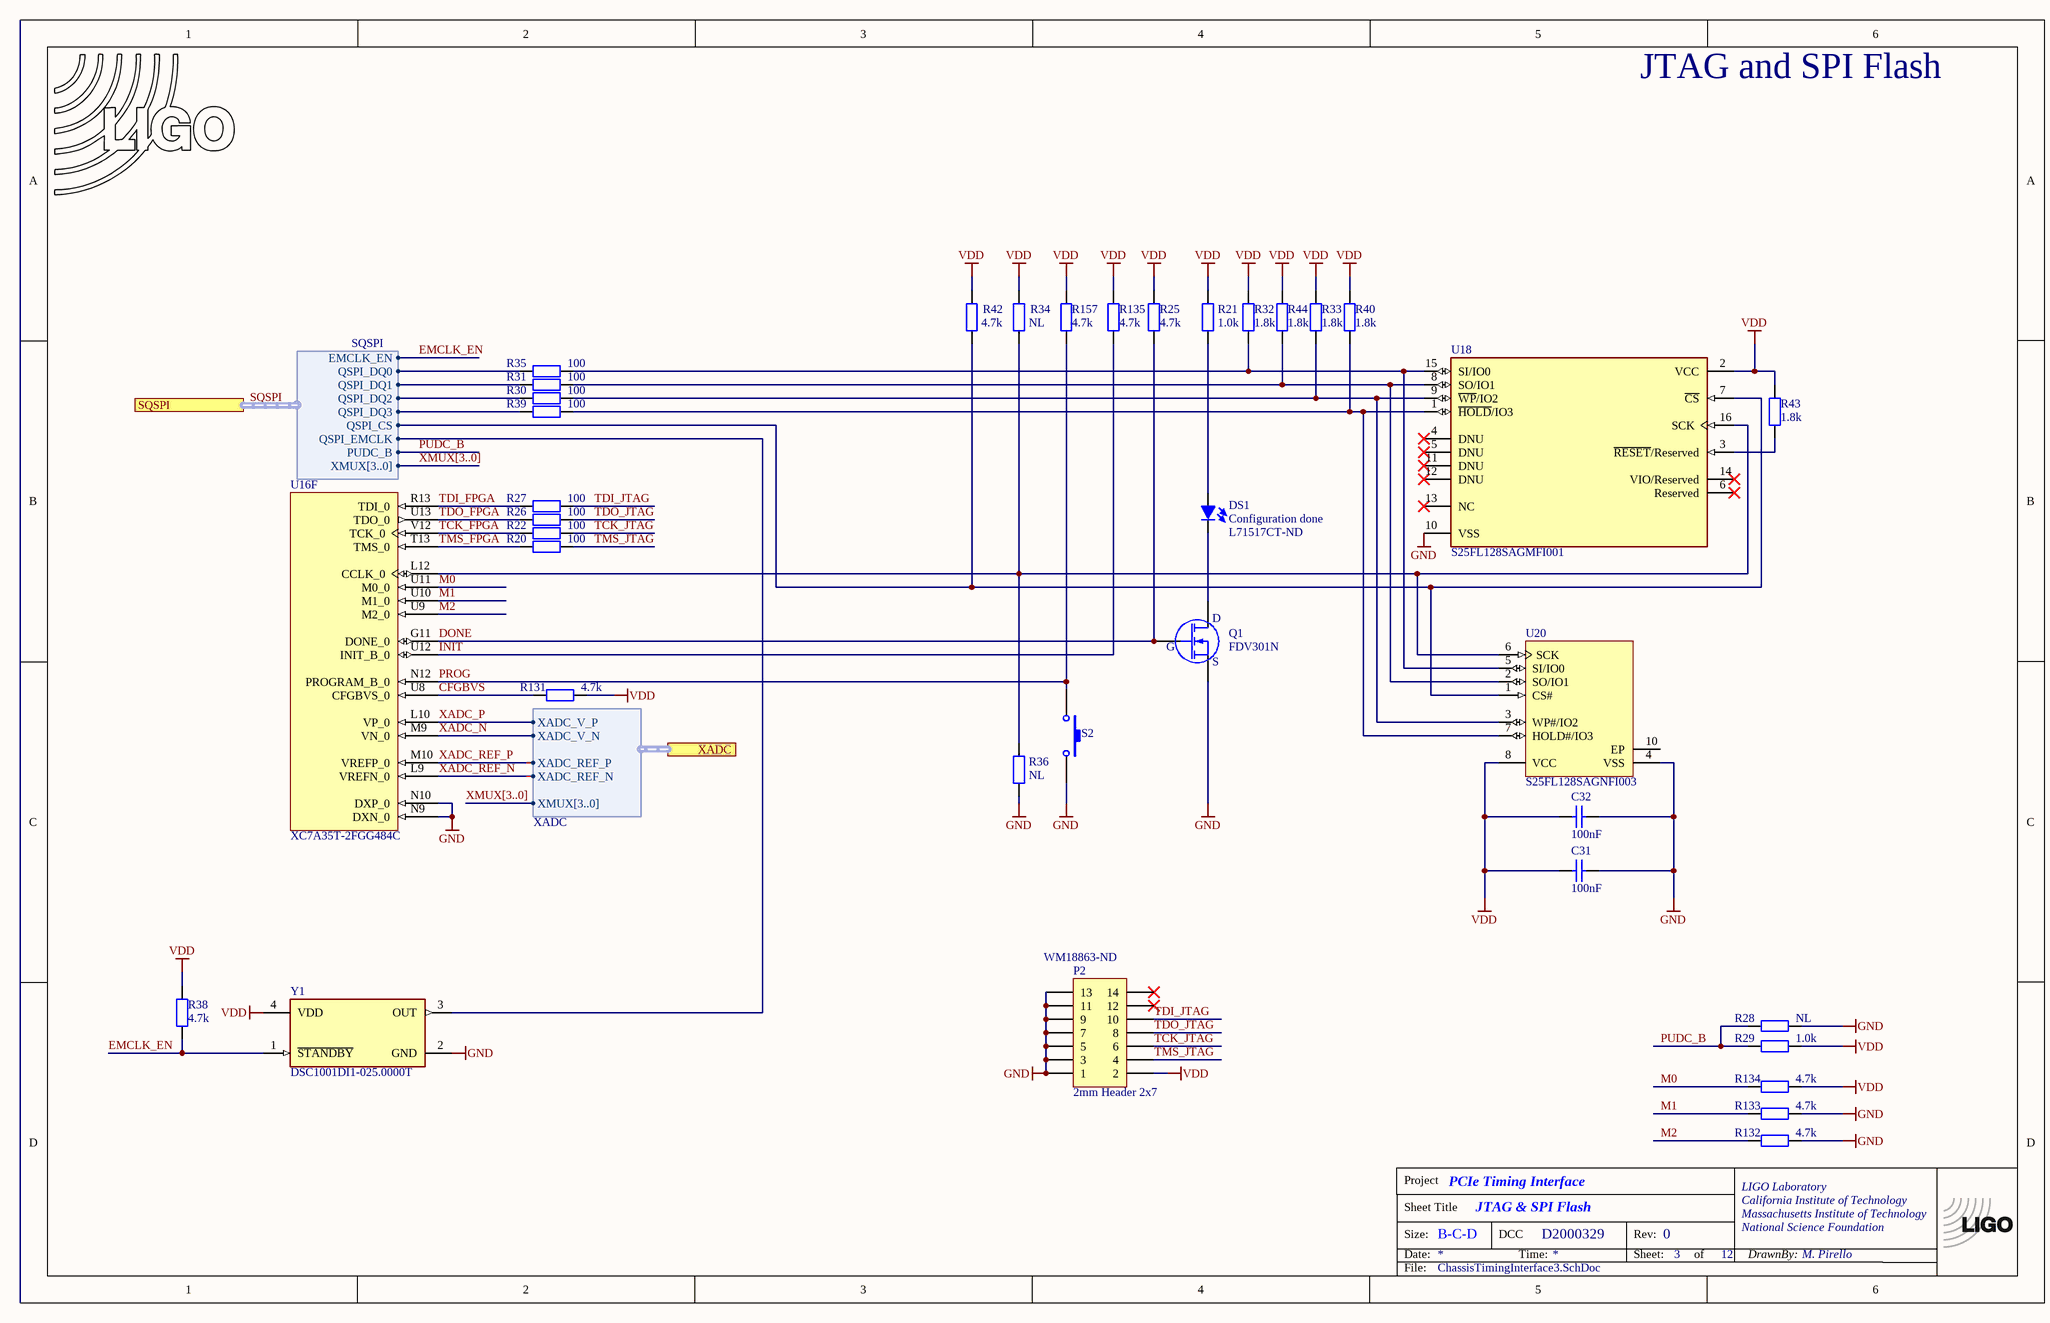
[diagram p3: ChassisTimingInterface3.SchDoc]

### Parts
(Parts that share a designator on the sheet are numbered #1, #2 ... from top to bottom, then left to right.)
*?#2  TitleBlock  (value not drawn)  (graphical)
C31  100nF  [CC1005-0402]
C32  100nF  [CC1005-0402]
DS1  Supplier Part Number 1: L71517CT-ND  [LED-0805]  (hidden comment: LED)
LOGO3  LIGO logo  [LIGO_LOGO]  (value not drawn)  (graphical)
P2  2mm Header 2x7  Supplier Part Number 1: WM18863-ND  [2MM_HDR2X7_RA]
Q1  FDV301N  [SO-G3/C2.25]
R20  100  [CR1608-0603]
R21  1.0k  [CR1608-0603]
R22  100  [CR1608-0603]
R25  4.7k  [CR1005-0402]
R26  100  [CR1608-0603]
R27  100  [CR1608-0603]
R28  NL  [CR1005-0402]
R29  1.0k  [CR1608-0603]
R30  100  [CR1608-0603]
R31  100  [CR1608-0603]
R32  1.8k  [CR1005-0402]
R33  1.8k  [CR1005-0402]
R34  NL  [CR1005-0402]
R35  100  [CR1608-0603]
R36  NL  [CR1005-0402]
R38  4.7k  [CR1005-0402]
R39  100  [CR1608-0603]
R40  1.8k  [CR1005-0402]
R42  4.7k  [CR1005-0402]
R43  1.8k  [CR1005-0402]
R44  1.8k  [CR1005-0402]
R131  4.7k  [CR1005-0402]
R132  4.7k  [CR1005-0402]
R133  4.7k  [CR1005-0402]
R134  4.7k  [CR1005-0402]
R135  4.7k  [CR1005-0402]
R157  4.7k  [CR1005-0402]
S2  B3SN-3112P  [SW_SMD_6MM]  (value not drawn)
U16  XC7A35T-2FGG484C  [FGG484]  (part F of 12)
U18  S25FL128SAGMFI001  [FP-002-15547-MFG]
U20  S25FL128SAGNFI003  [SPSN-WSON-8_L]
Y1  DSC1001DI1-025.0000T  [FP-CDFN2520-4LD-PL-1-MFG]

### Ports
SQSPI (harness SQSPI), XADC (harness XADC)

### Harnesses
SQSPI: QSPI_DQ0, QSPI_DQ1, QSPI_DQ2, QSPI_DQ3, QSPI_CS, QSPI_EMCLK, PUDC_B, XMUX[3..0], EMCLK_EN
XADC: XADC_REF_P, XADC_V_N, XADC_V_P, XMUX[3..0], XADC_REF_N

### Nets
GND: C31.1 C32.1 P2.1 P2.3 P2.5 P2.7 P2.9 P2.11 P2.13 Q1.2(S) R28.2 R36.2 R132.2 R133.2 S2.3 S2.5 U16.N9(DXN_0) U16.N10(DXP_0) U18.10(VSS) U20.4(VSS) Y1.2(GND)
VDD: C31.2 C32.2 P2.2 R21.1 R25.2 R29.2 R32.2 R33.2 R34.1 R38.1 R40.2 R42.1 R43.2 R44.2 R131.2 R134.2 R135.2 R157.2 U18.2(VCC) U20.8(VCC) Y1.4(VDD)
CFGBVS: R131.1 U16.U8(CFGBVS_0)
DONE: Q1.1(G) R25.1 U16.G11(DONE_0)
EMCLK_EN: R38.2 Y1.1(~{STANDBY}) ; port SQSPI.EMCLK_EN  [project net SQSPI.EMCLK_EN]
INIT: R135.1 U16.U12(INIT_B_0)
M0: R134.1 U16.U11(M0_0)
M1: R133.1 U16.U10(M1_0)
M2: R132.1 U16.U9(M2_0)
PROG: R157.1 S2.1 U16.N12(PROGRAM_B_0)
PUDC_B: R28.1 R29.1 ; port SQSPI.PUDC_B  [project net SQSPI.PUDC_B]
SQSPI.QSPI_CS: R42.2 U18.7(~{CS}) U20.1(CS#) ; port SQSPI.QSPI_CS
SQSPI.QSPI_DQ0: R35.2 ; port SQSPI.QSPI_DQ0
SQSPI.QSPI_DQ1: R31.2 ; port SQSPI.QSPI_DQ1
SQSPI.QSPI_DQ2: R30.2 ; port SQSPI.QSPI_DQ2
SQSPI.QSPI_DQ3: R39.2 ; port SQSPI.QSPI_DQ3
SQSPI.QSPI_EMCLK: Y1.3(OUT) ; port SQSPI.QSPI_EMCLK
TCK_FPGA: R22.2 U16.V12(TCK_0)
TCK_JTAG: P2.6 R22.1
TDI_FPGA: R27.2 U16.R13(TDI_0)
TDI_JTAG: P2.10 R27.1
TDO_FPGA: R26.2 U16.U13(TDO_0)
TDO_JTAG: P2.8 R26.1
TMS_FPGA: R20.2 U16.T13(TMS_0)
TMS_JTAG: P2.4 R20.1
XADC_N: U16.M9(VN_0) ; port XADC.XADC_V_N  [project net XADC.XADC_V_N]
XADC_P: U16.L10(VP_0) ; port XADC.XADC_V_P  [project net XADC.XADC_V_P]
XADC_REF_N: U16.L9(VREFN_0) ; port XADC.XADC_REF_N  [project net XADC.XADC_REF_N]
XADC_REF_P: U16.M10(VREFP_0) ; port XADC.XADC_REF_P  [project net XADC.XADC_REF_P]
NetDS1_1: DS1.1(K) Q1.3(D)
NetDS1_2: DS1.2(A) R21.2
NetR30_1: R30.1 R33.1 U18.9(~{WP}/IO2) U20.3(WP#/IO2)
NetR31_1: R31.1 R44.1 U18.8(SO/IO1) U20.2(SO/IO1)
NetR32_1: R32.1 R35.1 U18.15(SI/IO0) U20.5(SI/IO0)
NetR34_2: R34.2 R36.1 U16.L12(CCLK_0) U18.16(SCK) U20.6(SCK)
NetR39_1: R39.1 R40.1 U18.1(~{HOLD}/IO3) U20.7(HOLD#/IO3)
NetR43_1: R43.1 U18.3(~{RESET}/Reserved)

Not connected (* = marked no-connect by the designer): P2 12* 14*; U18 4(DNU)* 5(DNU)* 6(Reserved)* 11(DNU)* 12(DNU)* 13(NC)* 14(VIO/Reserved)*; U20 10(EP)

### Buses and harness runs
bus XMUX[3..0]
harness SQSPI = port SQSPI

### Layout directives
differential pair: XADC.XADC_REF_N, XADC.XADC_REF_P

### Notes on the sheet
- JTAG and SPI Flash
- (near DS1) Configuration done

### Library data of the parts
C31 C32 = ChipCap: as C39 on sheet ChassisTimingInterface2
DS1 = LED: Panel mount LED
LOGO3 = LIGO_logo
P2 = Xilinx_JTAG_Header: Xilinx JTAG header, 7-Pin, Dual row
Q1 = FDV301N: FDV301N, Digital FET, N-channel, SOT23; Part Number: FDV301NCT-ND
R20 R22 R26 R27 R30 R31 R35 R39 = ChipRes1: R0603 100; Part Number: RR08P100DCT-ND; Tolerance: 0.1%
R21 R29 = ChipRes1: as R87 on sheet ChassisTimingInterface2
R25 R38 R42 R131-R135 R157 = ChipRes1: as R109 on sheet ChassisTimingInterface4
R28 R34 R36 = ChipRes1: Resistor, surface mount; Tolerance: 0.1%
R32 R33 R40 R43 R44 = ChipRes1: R0402 1.8k; Part Number: RR05P1.8KDCT-ND; Tolerance: 0.1%
S2 = B3SN-3112P: Switch, SMD, 6mm; Part Number: SW262CT-ND
U16 = CMP-0383-00019-1: Artix-7 FPGA, 250 User I/Os, 4 GTP, 484-Ball BGA, Speed Grade 2, Commercial Grade, Pb-Free
U18 = CMP-12948-000005-1: IC FLASH 128M SPI 133MHZ 16SOIC; Part Number: 1274-1001-ND
U20 = CMP-1329-00027-1: MirrorBit Flash Non-Volatile Memory CMOS 3.0 Volt Core with Versatile I/O, Serial Peripheral Interface with Multi-I/O, 128 Mbit, 133 MHz, -40 to 85 degC, 8-Pin WSON (WNG008), RoHS, Tape and Reel; Part Number: 428-4003-1-ND
Y1 = CMP-06255-000005-1: MEMS OSC XO 25.0000MHZ CMOS SMD; Part Number: 576-4966-5-ND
